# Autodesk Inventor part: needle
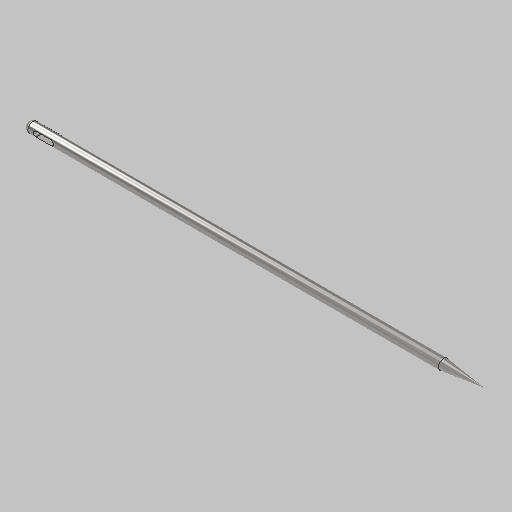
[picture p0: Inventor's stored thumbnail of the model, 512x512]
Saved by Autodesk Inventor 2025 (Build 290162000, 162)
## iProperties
Created: 2025-01
Part Number: needle
Material: Stainless Steel
Document SubType Name: Modeling
Designer: dansp
Density: 8 g/cm^3
Appearance: Semi-Polished
Mass: 0.257689 g
Surface Area: 1.37232 cm^2
Volume: 0.0322111 cm^3
Author: dansp
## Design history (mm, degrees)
sketch "Sketch1"
  geometry: L1 (0, 0.6)-(0, -0.1) reference; L2 (-9, 0)-(54, 0) reference; L3 (0, 0)-(0, 0.5); L4 (0, 0.5)-(45, 0.5); L5 (45, 0.5)-(45, 0); L6 (45, 0)-(41, 0.5)
  constraints: 8 end point, 3 point on line, 1 horizontal, 1 perpendicular
  dimensions: "d0" = 1 diameter of L4 L2; "d1" = 4 horizontal distance of L5.end L6.end; "d2" = 45 distance of L3.end L4.end
revolve "Revolution1" sketch "Sketch1" stored, may be unused: angle "d3" = 90 deg
sketch "Sketch2"
  geometry: L1 (1.25, 0)-(2.75, 0); L2 (1.25, -0.25)-(2.75, -0.25); L3 (2.75, 0.25)-(1.25, 0.25); L4 (0, 0.7)-(0, -0.7) reference; L5 (-9, 0)-(54, 0) reference; A1 r 0.25 centre (1.25, 0) between (1.25, 0.25) and (1.25, -0.25); A2 r 0.25 centre (2.75, 0) between (2.75, -0.25) and (2.75, 0.25); 4 further points
  constraints: 8 end point, 6 point on circle, 4 tangent, 2 centre point, 1 horizontal, 1 midpoint, 1 parallel, 1 point on line
  dimensions: "d4" = 2 distance of point (1, 0) point (3, 0); "d5" = 1 distance from line of point (1, 0) L4; "d6" = 0.5 distance between parallel lines of L2 L3
extrude "Extrusion1" cut sketch "Sketch2" extent not by distance; stored distance "d7" = 0; taper "d8" = 0 deg
fillet "Fillet1" dims "d9" = 0.5
body "Solid1"
